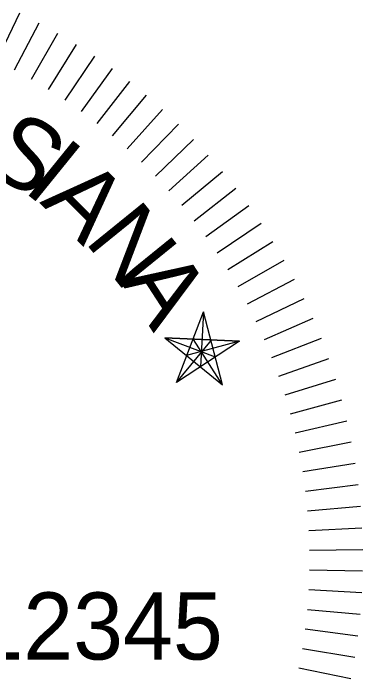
# Model space of a CAD drawing. Extents: x 0.19 to 2.82, y 0.04 to 1.79.
# Drawn here: x 2.3498 to 2.3889, y 0.8539 to 0.9283 of the extents above; entities that cross this region are included whole.
import ezdxf

# ---------------------------------------------------------------- set-up
doc = ezdxf.new("R2010")
doc.units = 0
doc.layers.add('Seal', color=7, linetype='Continuous')

msp = doc.modelspace()

# ---------------------------------------------------------------- linework, layer by layer
at = {"layer": 'Seal'}
for p, q in [((2.350527, 0.928251), (2.347957, 0.922901)), ((2.352687, 0.927166), (2.349928, 0.92191)), ((2.354807, 0.926004), (2.351862, 0.92085)), ((2.356885, 0.924767), (2.353758, 0.919722)), ((2.358917, 0.923457), (2.355612, 0.918526)), ((2.360901, 0.922075), (2.357422, 0.917265)), ((2.362834, 0.920623), (2.359186, 0.915941)), ((2.364714, 0.919103), (2.360901, 0.914554)), ((2.366539, 0.917517), (2.362566, 0.913107)), ((2.368306, 0.915866), (2.364178, 0.911601)), ((2.370013, 0.914154), (2.365736, 0.910039)), ((2.371658, 0.912382), (2.367236, 0.908422)), ((2.373239, 0.910552), (2.368678, 0.906753)), ((2.374753, 0.908667), (2.37006, 0.905033)), ((2.376199, 0.90673), (2.371379, 0.903265)), ((2.377575, 0.904741), (2.372634, 0.901451)), ((2.378879, 0.902705), (2.373824, 0.899594)), ((2.38011, 0.900624), (2.374947, 0.897695)), ((2.381265, 0.8985), (2.376001, 0.895757)), ((2.382344, 0.896337), (2.376986, 0.893783)), ((2.368114, 0.886998), (2.371126, 0.894875)), ((2.371126, 0.894875), (2.370778, 0.888735)), ((2.37325, 0.886728), (2.371126, 0.894875)), ((2.383345, 0.894136), (2.377899, 0.891775)), ((2.366802, 0.891979), (2.375142, 0.891593)), ((2.366802, 0.891979), (2.372439, 0.889855)), ((2.375142, 0.891593), (2.366802, 0.891979)), ((2.366802, 0.891979), (2.37325, 0.886728)), ((2.375142, 0.891593), (2.366802, 0.891979)), ((2.366802, 0.891979), (2.372439, 0.889855)), ((2.368114, 0.886998), (2.372015, 0.891709)), ((2.37325, 0.886728), (2.370006, 0.891786)), ((2.384267, 0.891901), (2.37874, 0.889736)), ((2.375142, 0.891593), (2.368114, 0.886998)), ((2.375142, 0.891593), (2.368114, 0.886998)), ((2.375142, 0.891593), (2.368114, 0.886998)), ((2.375142, 0.891593), (2.369235, 0.89001)), ((2.385108, 0.889634), (2.379508, 0.887668)), ((2.385868, 0.887339), (2.380201, 0.885574)), ((2.386546, 0.885018), (2.380819, 0.883456)), ((2.38714, 0.882674), (2.381362, 0.881318)), ((2.387651, 0.880311), (2.381827, 0.879162)), ((2.388076, 0.877931), (2.382216, 0.87699)), ((2.388417, 0.875537), (2.382526, 0.874806)), ((2.388672, 0.873133), (2.382759, 0.872612)), ((2.38884, 0.870721), (2.382913, 0.870412)), ((2.388923, 0.868304), (2.382988, 0.868207)), ((2.388919, 0.865886), (2.382985, 0.866001)), ((2.388829, 0.86347), (2.382903, 0.863797)), ((2.388653, 0.861059), (2.382742, 0.861597)), ((2.388391, 0.858655), (2.382503, 0.859404)), ((2.388043, 0.856263), (2.382185, 0.857221)), ((2.38761, 0.853884), (2.38179, 0.855051))]:
    msp.add_line(p, q, dxfattribs=at)

# ---------------------------------------------------------------- texts
for s, rotation, p in [('S', 327.00013, (2.346277, 0.911177)), ('I', 321.00012, (2.350813, 0.908486)), ('A', 315.0001, (2.352732, 0.907103)), ('N', 309.00009, (2.357709, 0.902815)), ('A', 303.00007, (2.361726, 0.898365))]:
    msp.add_text(s, height=0.0079, rotation=rotation, dxfattribs=at).set_placement(p)
msp.add_text('License No. 12345', height=0.0075, dxfattribs=at).set_placement((2.289639, 0.856024))

doc.saveas('drawing.dxf')
